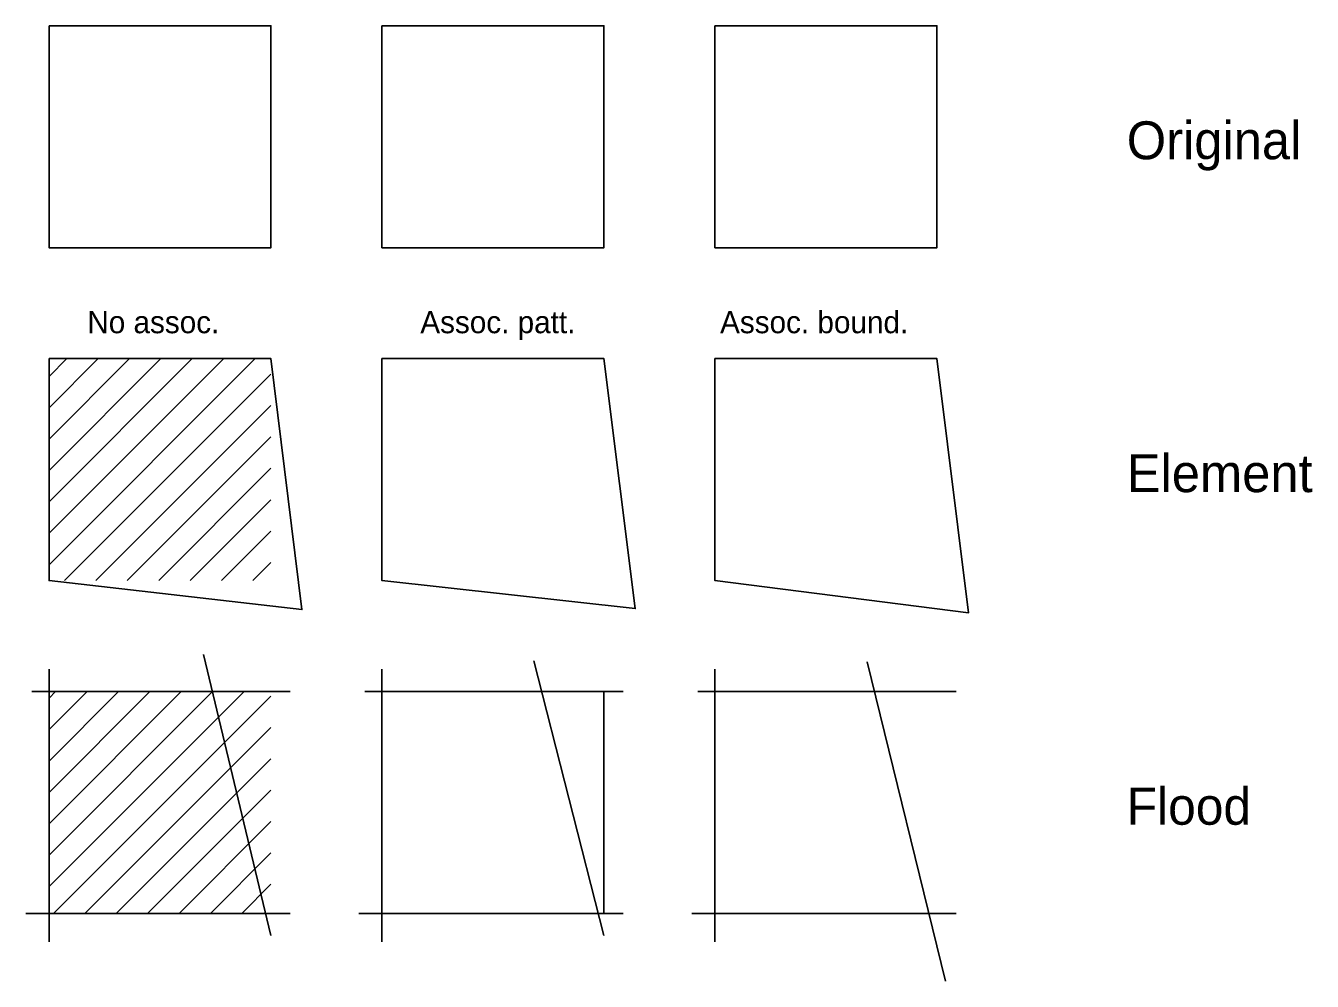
# Model space of a CAD drawing. Extents: x 0.17 to 5.97, y 0.38 to 4.68.
import ezdxf

# ---------------------------------------------------------------- set-up
doc = ezdxf.new("R2010")
doc.units = 0
doc.layers.add('Default', color=7, linetype='Continuous')

msp = doc.modelspace()

# ---------------------------------------------------------------- linework, layer by layer
at = {"layer": 'Default'}
for p, q in [((0.2783, 2.252), (1.2067, 3.1804)), ((0.2783, 2.3935), (1.0653, 3.1804)), ((0.2783, 2.5349), (0.9239, 3.1804)), ((0.2783, 2.6763), (0.7824, 3.1804)), ((0.2783, 2.8177), (0.641, 3.1804)), ((0.2783, 2.9591), (0.4996, 3.1804)), ((0.2783, 3.1006), (0.3582, 3.1804)), ((0.3481, 2.1804), (1.2783, 3.1106)), ((0.4895, 2.1804), (1.2783, 2.9692)), ((0.631, 2.1804), (1.2783, 2.8278)), ((0.7724, 2.1804), (1.2783, 2.6863)), ((0.9138, 2.1804), (1.2783, 2.5449)), ((1.0552, 2.1804), (1.2783, 2.4035)), ((1.1966, 2.1804), (1.2783, 2.2621)), ((0.9748, 1.8475), (1.2783, 0.5809)), ((2.4624, 1.8193), (2.7783, 0.5809)), ((3.9641, 1.8146), (4.317, 0.3752)), ((0.2783, 0.5526), (0.2783, 1.7818)), ((1.7783, 0.5526), (1.7783, 1.7818)), ((3.2783, 0.5526), (3.2783, 1.7818)), ((0.2017, 1.6804), (1.3645, 1.6804)), ((0.2783, 0.802), (1.1568, 1.6804)), ((0.2783, 0.9434), (1.0154, 1.6804)), ((0.2783, 1.0848), (0.8739, 1.6804)), ((0.2783, 1.2262), (0.7325, 1.6804)), ((0.2783, 1.3676), (0.5911, 1.6804)), ((0.2783, 1.5091), (0.4497, 1.6804)), ((0.2783, 1.6505), (0.3082, 1.6804)), ((0.2982, 0.6804), (1.2783, 1.6605)), ((1.7017, 1.6804), (2.8645, 1.6804)), ((2.7783, 1.6804), (1.7783, 1.6804)), ((1.7783, 1.6804), (1.7783, 0.6804)), ((2.7783, 0.6804), (2.7783, 1.6804)), ((3.2017, 1.6804), (4.3645, 1.6804)), ((0.4396, 0.6804), (1.2783, 1.5191)), ((0.581, 0.6804), (1.2783, 1.3777)), ((0.7225, 0.6804), (1.2783, 1.2363)), ((0.8639, 0.6804), (1.2783, 1.0949)), ((1.0053, 0.6804), (1.2783, 0.9534)), ((1.1467, 0.6804), (1.2783, 0.812)), ((1.3645, 0.6804), (0.1735, 0.6804)), ((2.8645, 0.6804), (1.6735, 0.6804)), ((1.7783, 0.6804), (2.7783, 0.6804)), ((4.3645, 0.6804), (3.1735, 0.6804))]:
    msp.add_line(p, q, dxfattribs=at)
for points in [[(0.2783, 4.6804), (1.2783, 4.6804), (1.2783, 3.6804), (0.2783, 3.6804)], [(1.7783, 4.6804), (2.7783, 4.6804), (2.7783, 3.6804), (1.7783, 3.6804)], [(3.2783, 4.6804), (4.2783, 4.6804), (4.2783, 3.6804), (3.2783, 3.6804)], [(0.2783, 3.1804), (1.2783, 3.1804), (1.4173, 2.05), (0.2783, 2.1804)], [(1.7783, 3.1804), (2.7783, 3.1804), (2.919, 2.0547), (1.7783, 2.1804)], [(3.2783, 3.1804), (4.2783, 3.1804), (4.4207, 2.0359), (3.2783, 2.1804)]]:
    msp.add_lwpolyline(points, close=True, dxfattribs=at)

# ---------------------------------------------------------------- texts
for s, height, p in [('Original', 0.17071, (5.1331, 4.0789)), ('No assoc.', 0.1, (0.4509, 3.295)), ('Assoc. patt.', 0.1, (1.9509, 3.295)), ('Assoc. bound.', 0.1, (3.3013, 3.295)), ('Element', 0.17071, (5.1331, 2.5789)), ('Flood', 0.16742, (5.1331, 1.0805))]:
    msp.add_text(s, height=height, dxfattribs=at).set_placement(p)

doc.saveas('drawing.dxf')
